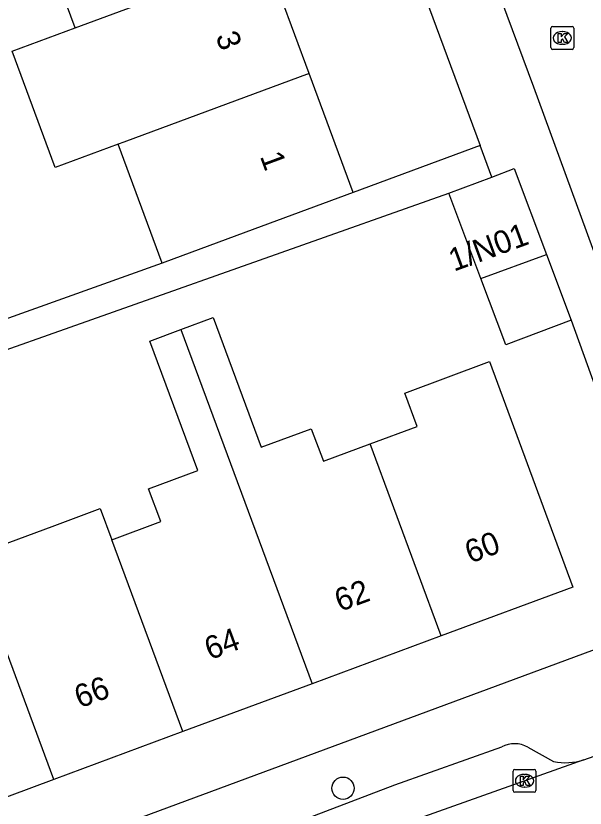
# Model space of a CAD drawing. Extents: x 158474 to 159560, y 388525 to 389605.
# Drawn here: x 159109.04 to 159133.94, y 388708.03 to 388742.68 of the extents above; entities that cross this region are included whole.
import ezdxf

# ---------------------------------------------------------------- set-up
doc = ezdxf.new("R2010")
doc.units = 0
for name, color, linetype in [('IMGEO_Boom', 7, 'Continuous'), ('IMGEO_Kolk', 7, 'Continuous'), ('IMGEO_Pand', 7, 'Continuous'), ('IMGEO_Pand_nummerreeks', 7, 'Continuous'), ('IMGEO_Rijbaan_lokaal_open', 7, 'Continuous'), ('IMGEO_Voetpad_open', 7, 'Continuous')]:
    doc.layers.add(name, color=color, linetype=linetype)

msp = doc.modelspace()

# ---------------------------------------------------------------- linework, layer by layer
at = {"layer": 'IMGEO_Boom'}
msp.add_circle((159123.349, 388708.895), 0.489, dxfattribs=at)
at = {"layer": 'IMGEO_Kolk'}
for p, q in [((159132.439, 388741.29), (159132.439, 388742.142)), ((159132.514, 388742.216), (159133.366, 388742.216)), ((159133.44, 388742.142), (159133.44, 388741.29)), ((159132.927, 388741.996), (159132.952, 388741.996)), ((159132.95, 388741.436), (159132.925, 388741.436)), ((159133.366, 388741.216), (159132.514, 388741.216)), ((159130.785, 388708.795), (159130.785, 388709.647)), ((159130.86, 388709.721), (159131.712, 388709.721)), ((159131.273, 388709.501), (159131.298, 388709.501)), ((159131.786, 388709.647), (159131.786, 388708.795)), ((159131.296, 388708.941), (159131.271, 388708.941)), ((159131.712, 388708.721), (159130.86, 388708.721))]:
    msp.add_line(p, q, dxfattribs=at)
for points in [[(159132.439, 388741.29), (159132.439, 388742.142)], [(159132.514, 388742.216), (159133.366, 388742.216)], [(159133.44, 388742.142), (159133.44, 388741.29)], [(159132.76, 388741.916), (159132.883, 388741.916), (159132.883, 388741.765), (159133.013, 388741.916), (159133.177, 388741.916), (159133.031, 388741.765), (159133.184, 388741.516), (159133.032, 388741.516), (159132.947, 388741.68), (159132.883, 388741.613), (159132.883, 388741.516), (159132.76, 388741.516), (159132.76, 388741.916)], [(159133.366, 388741.216), (159132.514, 388741.216)], [(159130.785, 388708.795), (159130.785, 388709.647)], [(159130.86, 388709.721), (159131.712, 388709.721)], [(159131.786, 388709.647), (159131.786, 388708.795)], [(159131.106, 388709.421), (159131.229, 388709.421), (159131.229, 388709.27), (159131.359, 388709.421), (159131.523, 388709.421), (159131.377, 388709.27), (159131.53, 388709.021), (159131.378, 388709.021), (159131.293, 388709.185), (159131.229, 388709.118), (159131.229, 388709.021), (159131.106, 388709.021), (159131.106, 388709.421)], [(159131.712, 388708.721), (159130.86, 388708.721)]]:
    msp.add_lwpolyline(points, dxfattribs=at)
for centre, start, end in [((159132.516, 388742.14), 91.552, 178.448), ((159132.516, 388742.14), 91.552, 178.448), ((159133.364, 388742.14), 1.552, 88.448), ((159133.364, 388742.14), 1.552, 88.448), ((159132.516, 388741.292), 181.552, 268.448), ((159132.516, 388741.292), 181.552, 268.448), ((159133.364, 388741.292), 271.552, 358.448), ((159133.364, 388741.292), 271.552, 358.448), ((159130.862, 388709.645), 91.552, 178.448), ((159130.862, 388709.645), 91.552, 178.448), ((159131.71, 388709.645), 1.552, 88.448), ((159131.71, 388709.645), 1.552, 88.448), ((159130.862, 388708.797), 181.552, 268.448), ((159130.862, 388708.797), 181.552, 268.448), ((159131.71, 388708.797), 271.552, 358.448), ((159131.71, 388708.797), 271.552, 358.448)]:
    msp.add_arc(centre, 0.0765, start, end, dxfattribs=at)
for centre, major_axis, ratio, start_param, end_param in [((159132.926, 388741.716), (-0.387, 0.002), 0.722429, 4.712389, 7.853982), ((159132.951, 388741.716), (-0.39, 0.002), 0.717154, 1.570796, 4.712389), ((159131.272, 388709.221), (-0.387, 0.002), 0.722429, 4.712389, 7.853982), ((159131.297, 388709.221), (-0.39, 0.002), 0.717154, 1.570796, 4.712389)]:
    msp.add_ellipse(centre, major_axis=major_axis, ratio=ratio, start_param=start_param, end_param=end_param, dxfattribs=at)
at = {"layer": 'IMGEO_Pand'}
for points in [[(159111.634, 388742.151), (159109.75, 388747.238)], [(159111.634, 388742.151), (159119.983, 388745.241)], [(159121.866, 388740.154), (159119.983, 388745.241)], [(159113.517, 388737.063), (159110.759, 388736.042), (159108.876, 388741.13), (159111.634, 388742.151)], [(159121.866, 388740.154), (159113.769, 388737.156), (159113.517, 388737.063)], [(159123.791, 388734.953), (159121.866, 388740.154)], [(159115.442, 388731.863), (159113.517, 388737.063)], [(159129.851, 388735.632), (159130.836, 388736.002), (159132.25, 388732.24)], [(159127.977, 388734.928), (159129.851, 388735.632)], [(159123.791, 388734.953), (159119.102, 388733.218), (159115.442, 388731.863)], [(159129.382, 388731.188), (159127.977, 388734.928)], [(159129.382, 388731.188), (159132.25, 388732.24)], [(159132.25, 388732.24), (159133.328, 388729.371)], [(159133.328, 388729.371), (159130.469, 388728.297), (159129.382, 388731.188)], [(159116.251, 388728.958), (159117.672, 388729.485), (159119.776, 388723.81), (159121.962, 388724.621), (159122.488, 388723.203), (159124.531, 388723.961)], [(159113.236, 388719.768), (159115.376, 388720.562), (159114.844, 388721.998), (159116.993, 388722.795), (159114.894, 388728.455), (159116.251, 388728.958)], [(159116.251, 388728.958), (159121.998, 388713.466)], [(159124.531, 388723.961), (159126.587, 388724.723), (159126.046, 388726.183), (159129.749, 388727.556), (159133.405, 388717.696), (159127.645, 388715.56)], [(159104.953, 388724.784), (159106.528, 388725.368), (159108.66, 388719.62), (159110.738, 388720.391), (159112.731, 388721.13), (159113.236, 388719.768)], [(159110.704, 388709.277), (159104.953, 388724.784)], [(159127.645, 388715.56), (159124.531, 388723.961)], [(159116.35, 388711.371), (159113.236, 388719.768)], [(159127.645, 388715.56), (159121.998, 388713.466)], [(159121.998, 388713.466), (159116.35, 388711.371)], [(159116.35, 388711.371), (159110.704, 388709.277)], [(159110.704, 388709.277), (159104.943, 388707.141), (159104.395, 388708.619)]]:
    msp.add_lwpolyline(points, dxfattribs=at)
at = {"layer": 'IMGEO_Rijbaan_lokaal_open'}
for points in [[(159139.87, 388717.199), (159131.692, 388739.556), (159130.295, 388743.326)], [(159133.876, 388710.139), (159134.579, 388710.389), (159139.387, 388712.169)], [(159133.876, 388710.139), (159126.21, 388707.414), (159121.757, 388705.716)]]:
    msp.add_lwpolyline(points, dxfattribs=at)
at = {"layer": 'IMGEO_Voetpad_open'}
for points in [[(159117.478, 388761.857), (159119.842, 388762.718), (159124.542, 388750), (159129.343, 388737.007)], [(159129.343, 388737.007), (159123.791, 388734.953)], [(159129.851, 388735.632), (159129.343, 388737.007)], [(159098.633, 388724.549), (159127.977, 388734.928)], [(159115.442, 388731.863), (159102.756, 388727.325)], [(159133.328, 388729.371), (159138.036, 388716.321)], [(159138.036, 388716.321), (159090.691, 388698.796)], [(159100.493, 388699.696), (159105.915, 388701.685), (159115.76, 388705.283), (159125.612, 388709.038), (159130.293, 388710.702)], [(159131.438, 388710.691), (159132.557, 388710.067)]]:
    msp.add_lwpolyline(points, dxfattribs=at)
for centre, radius, start, end in [((159130.856, 388709.667), 1.178, 60.3666, 118.5325), ((159133.079, 388712.619), 2.605, 258.4376, 287.8114)]:
    msp.add_arc(centre, radius, start, end, dxfattribs=at)

# ---------------------------------------------------------------- texts
at = {"layer": 'IMGEO_Pand_nummerreeks'}
for s, rotation, p in [('3', 290.3111, (159117.763, 388741.789)), ('1', 290.3111, (159119.706, 388736.538)), ('1/N01', 20.1906, (159128.197, 388731.487)), ('60', 20.3471, (159128.91, 388718.718)), ('62', 20.3471, (159123.212, 388716.605)), ('64', 20.3471, (159117.523, 388714.495)), ('66', 20.3457, (159111.831, 388712.383))]:
    msp.add_text(s, height=1, rotation=rotation, dxfattribs=at).set_placement(p)

doc.saveas('drawing.dxf')
